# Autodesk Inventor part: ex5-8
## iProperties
Author: Administrator
Created: 2001-09
Part Number: ex5-8
Document SubType Name: Modeling
Designer: Administrator
Control State: 0
Master: False
Checked Out: False
PropertySet Name: Design Tracking Control
Length Units: 11272
Angle Units: 11279
Time Units: 11290
Mass Units: 11286
Shininess: 3
Angle Display Precision: 2
Document Length Units: 11272
Document Angle Units: 11286
Document Time Units: 11279
Document Mass Units: 11290
Document Length Units Precision: 3
Document Angle Units Precision: 2
Compacted: False
PropertySet Name: _Private Model Information
Density: 0.0
Volumn: 0.0
Area: 0.0
PropertySet Name: Model Information
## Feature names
1. Revolution1
2. Hole1
3. Shell1
4. Loft1
5. Sweep1
6. Coil1
